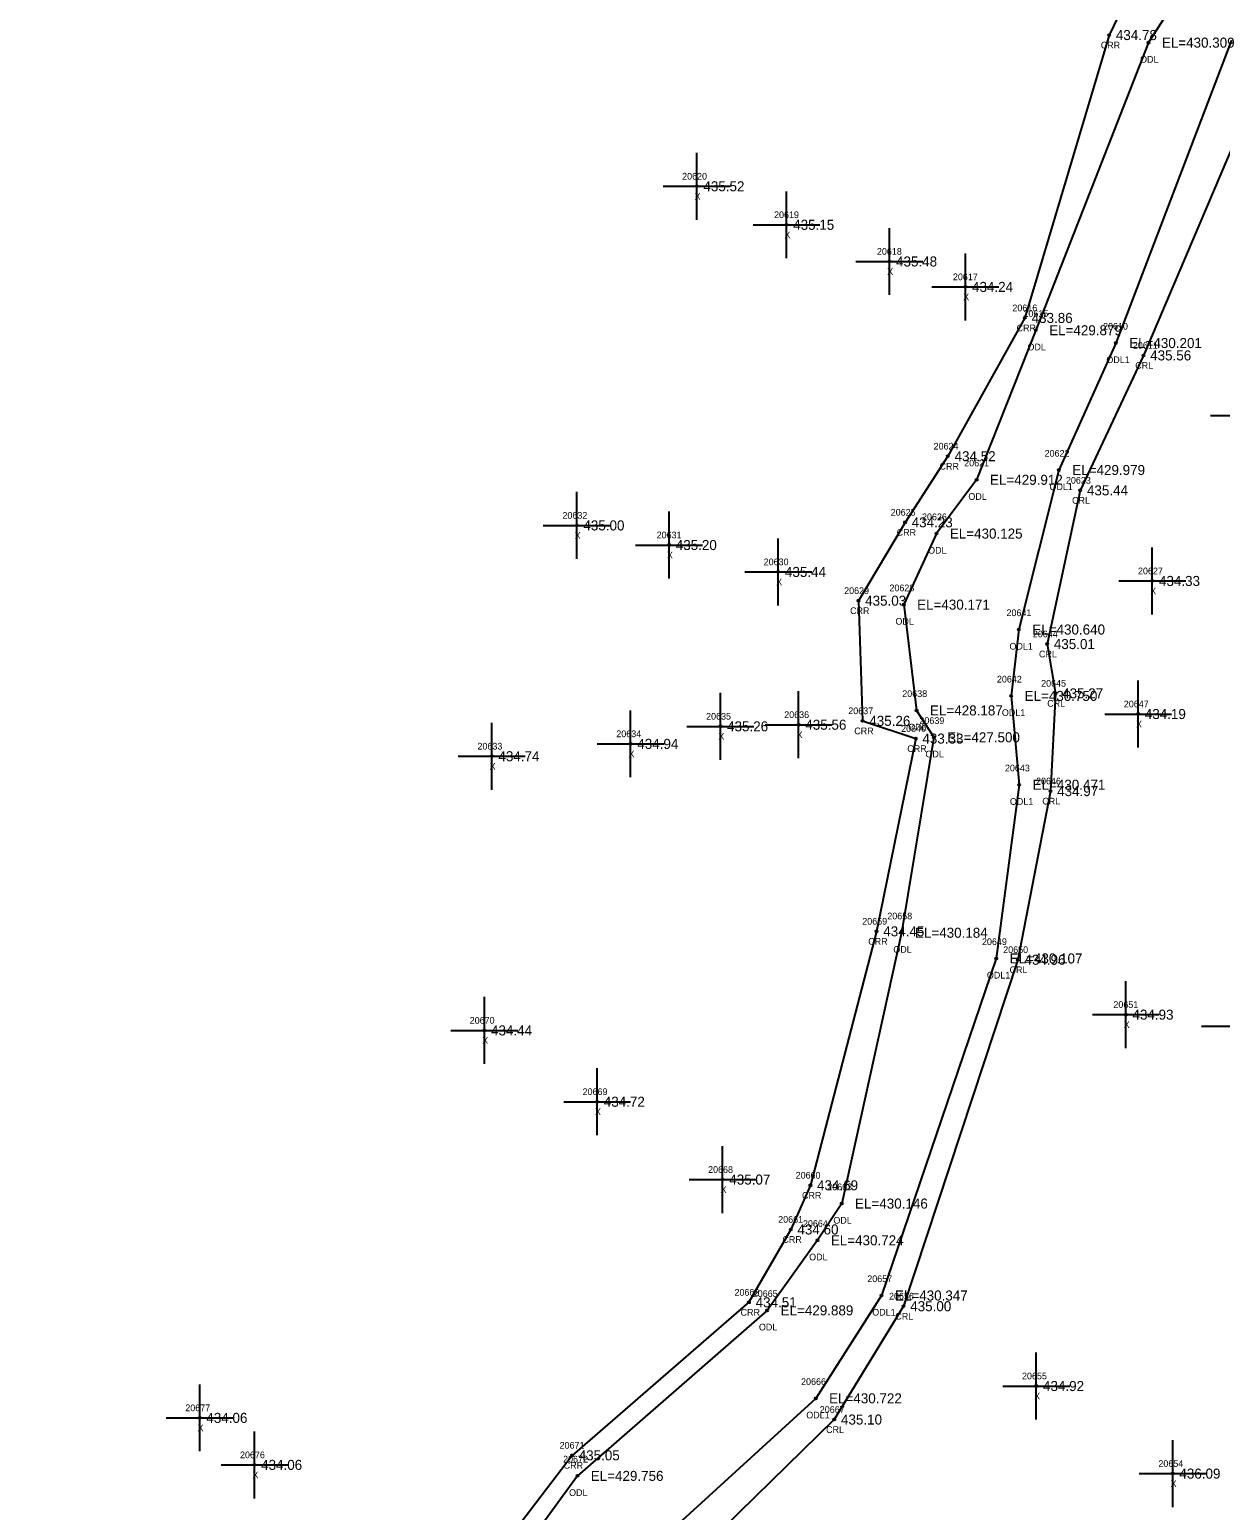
# Model space of a CAD drawing. Extents: x 1613836 to 1615109, y 777151 to 778248.
# Drawn here: x 1614274.4 to 1614452.4, y 777451 to 777672.3 of the extents above; entities that cross this region are included whole.
import ezdxf

# ---------------------------------------------------------------- set-up
doc = ezdxf.new("R2010")
doc.units = 0
for name, color, linetype in [('RD_EX_H2O', 7, 'Continuous'), ('RD_EX_H2O_txCode', 7, 'Continuous'), ('RD_EX_Misc', 7, 'Continuous'), ('RD_EX_Misc_txCode', 7, 'Continuous'), ('RD_EX_TX_H2O_ELEV', 7, 'Continuous'), ('RD_EX_TX_Misc_ELEV', 7, 'Continuous'), ('RD_SMD_Locator', 7, 'Continuous')]:
    doc.layers.add(name, color=color, linetype=linetype)

msp = doc.modelspace()

# ---------------------------------------------------------------- linework, layer by layer
at = {"layer": 'RD_EX_H2O'}
for points in [[(1614444.52, 777689.77), (1614435.76, 777671.49), (1614423.17, 777629.21), (1614411.65, 777608.54), (1614405.24, 777598.66), (1614398.28, 777586.95), (1614398.9, 777568.99), (1614406.84, 777566.34), (1614400.99, 777537.53), (1614391.09, 777499.57), (1614388.16, 777492.97), (1614381.91, 777482.08), (1614355.46, 777459.21), (1614337.74, 777435.91)], [(1614451.34, 777685.51), (1614441.64, 777670.36), (1614424.79, 777627.37), (1614415.95, 777605.02), (1614409.94, 777596.98), (1614405.05, 777586.36), (1614406.98, 777570.55), (1614409.54, 777566.53), (1614404.73, 777537.32), (1614395.77, 777496.84), (1614392.15, 777491.35), (1614384.64, 777480.88), (1614356.26, 777456.14), (1614340.53, 777434.54)], [(1614454.05, 777670.72), (1614436.75, 777625.46), (1614428.25, 777606.48), (1614422.27, 777582.64), (1614421.12, 777572.72), (1614422.32, 777559.44), (1614418.89, 777533.48), (1614401.74, 777483.1), (1614391.89, 777467.73), (1614349.64, 777429.15), (1614339.78, 777409.85), (1614335.95, 777396.86), (1614325.72, 777389.21), (1614290.49, 777368.16), (1614258.86, 777343.9), (1614240.94, 777335.51), (1614216.63, 777330.83), (1614183.69, 777312.56), (1614168.44, 777300.41), (1614159.13, 777291.4), (1614144.06, 777280.87), (1614131.88, 777280.26), (1614120.23, 777291.04), (1614099.45, 777295.34)], [(1614459.87, 777668.19), (1614440.89, 777623.61), (1614431.44, 777603.44), (1614426.49, 777580.47), (1614427.73, 777573.1), (1614426.99, 777558.49), (1614422.1, 777533.28), (1614405.02, 777481.5), (1614394.67, 777464.56), (1614354.26, 777425.05), (1614343.94, 777405.8), (1614336.19, 777392.32), (1614327.17, 777384), (1614294.72, 777361.79), (1614260.51, 777340.05), (1614241.21, 777332.56), (1614218.51, 777327.29), (1614184.87, 777310.82), (1614170.3, 777296.09), (1614164.11, 777287.12), (1614144.8, 777274.41), (1614131.24, 777274.67), (1614118.95, 777276.86), (1614096.34, 777283.46)]]:
    msp.add_lwpolyline(points, dxfattribs=at)
at = {"layer": 'RD_EX_Misc'}
for p, q in [((1614374.1, 777643.89), (1614374.1, 777653.89)), ((1614369.1, 777648.89), (1614379.1, 777648.89)), ((1614387.52, 777638.13), (1614387.52, 777648.13)), ((1614382.52, 777643.13), (1614392.52, 777643.13)), ((1614402.9, 777632.65), (1614402.9, 777642.65)), ((1614414.26, 777628.85), (1614414.26, 777638.85)), ((1614397.9, 777637.65), (1614407.9, 777637.65)), ((1614409.26, 777633.85), (1614419.26, 777633.85)), ((1614450.89, 777614.61), (1614460.89, 777614.61)), ((1614356.16, 777593.2), (1614356.16, 777603.2)), ((1614369.97, 777590.27), (1614369.97, 777600.27)), ((1614351.16, 777598.2), (1614361.16, 777598.2)), ((1614386.29, 777586.25), (1614386.29, 777596.25)), ((1614364.97, 777595.27), (1614374.97, 777595.27)), ((1614442.21, 777584.9), (1614442.21, 777594.9)), ((1614381.29, 777591.25), (1614391.29, 777591.25)), ((1614437.21, 777589.9), (1614447.21, 777589.9)), ((1614440.09, 777565.01), (1614440.09, 777575.01)), ((1614377.64, 777563.17), (1614377.64, 777573.17)), ((1614389.34, 777563.41), (1614389.34, 777573.41)), ((1614364.22, 777560.55), (1614364.22, 777570.55)), ((1614435.09, 777570.01), (1614445.09, 777570.01)), ((1614343.46, 777558.7), (1614343.46, 777568.7)), ((1614372.64, 777568.17), (1614382.64, 777568.17)), ((1614384.34, 777568.41), (1614394.34, 777568.41)), ((1614359.22, 777565.55), (1614369.22, 777565.55)), ((1614338.46, 777563.7), (1614348.46, 777563.7)), ((1614438.25, 777520.08), (1614438.25, 777530.08)), ((1614342.35, 777517.72), (1614342.35, 777527.72)), ((1614433.25, 777525.08), (1614443.25, 777525.08)), ((1614449.55, 777523.38), (1614459.55, 777523.38)), ((1614337.35, 777522.72), (1614347.35, 777522.72)), ((1614359.21, 777507.06), (1614359.21, 777517.06)), ((1614354.21, 777512.06), (1614364.21, 777512.06)), ((1614377.97, 777495.43), (1614377.97, 777505.43)), ((1614372.97, 777500.43), (1614382.97, 777500.43)), ((1614424.87, 777464.57), (1614424.87, 777474.57)), ((1614299.79, 777459.81), (1614299.79, 777469.81)), ((1614419.87, 777469.57), (1614429.87, 777469.57)), ((1614294.79, 777464.81), (1614304.79, 777464.81)), ((1614307.98, 777452.78), (1614307.98, 777462.78)), ((1614445.26, 777451.48), (1614445.26, 777461.48)), ((1614302.98, 777457.78), (1614312.98, 777457.78)), ((1614440.26, 777456.48), (1614450.26, 777456.48))]:
    msp.add_line(p, q, dxfattribs=at)
at = {"layer": 'RD_SMD_Locator'}
for centre in [(1614435.76, 777671.49), (1614441.64, 777670.36), (1614374.1, 777648.89), (1614387.52, 777643.13), (1614402.9, 777637.65), (1614414.26, 777633.85), (1614423.17, 777629.21), (1614424.79, 777627.37), (1614436.75, 777625.46), (1614440.89, 777623.61), (1614411.65, 777608.54), (1614415.95, 777605.02), (1614428.25, 777606.48), (1614431.44, 777603.44), (1614356.16, 777598.2), (1614405.24, 777598.66), (1614409.94, 777596.98), (1614369.97, 777595.27), (1614386.29, 777591.25), (1614442.21, 777589.9), (1614398.28, 777586.95), (1614405.05, 777586.36), (1614422.27, 777582.64), (1614426.49, 777580.47), (1614421.12, 777572.72), (1614427.73, 777573.1), (1614406.98, 777570.55), (1614440.09, 777570.01), (1614377.64, 777568.17), (1614389.34, 777568.41), (1614398.9, 777568.99), (1614364.22, 777565.55), (1614406.84, 777566.34), (1614409.54, 777566.53), (1614343.46, 777563.7), (1614422.32, 777559.44), (1614426.99, 777558.49), (1614400.99, 777537.53), (1614404.73, 777537.32), (1614418.89, 777533.48), (1614422.1, 777533.28), (1614438.25, 777525.08), (1614342.35, 777522.72), (1614359.21, 777512.06), (1614377.97, 777500.43), (1614391.09, 777499.57), (1614395.77, 777496.84), (1614388.16, 777492.97), (1614392.15, 777491.35), (1614401.74, 777483.1), (1614381.91, 777482.08), (1614384.64, 777480.88), (1614405.02, 777481.5), (1614424.87, 777469.57), (1614391.89, 777467.73), (1614299.79, 777464.81), (1614394.67, 777464.56), (1614355.46, 777459.21), (1614307.98, 777457.78), (1614445.26, 777456.48), (1614356.26, 777456.14)]:
    msp.add_circle(centre, 0.15, dxfattribs=at)

# ---------------------------------------------------------------- texts
at = {"layer": 'RD_EX_H2O_txCode'}
for s, p in [('CRR', (1614434.51, 777669.49)), ('ODL', (1614440.39, 777667.36)), ('20616', (1614421.29, 777630.21)), ('20615', (1614422.94, 777629.37)), ('CRR', (1614421.92, 777627.21)), ('20610', (1614434.85, 777627.46)), ('ODL', (1614423.55, 777624.37)), ('20611', (1614439.31, 777624.61)), ('ODL1', (1614435.34, 777622.46)), ('CRL', (1614439.66, 777621.61)), ('20624', (1614409.51, 777609.54)), ('20622', (1614426.11, 777608.48)), ('CRR', (1614410.4, 777606.54)), ('20621', (1614414.09, 777607.02)), ('20623', (1614429.3, 777604.44)), ('ODL', (1614414.71, 777602.02)), ('ODL1', (1614426.84, 777603.48)), ('20625', (1614403.1, 777599.66)), ('CRL', (1614430.21, 777601.44)), ('20626', (1614407.78, 777598.98)), ('CRR', (1614403.99, 777596.66)), ('ODL', (1614408.7, 777593.98)), ('20628', (1614402.91, 777588.36)), ('20629', (1614396.14, 777587.95)), ('CRR', (1614397.03, 777584.95)), ('20641', (1614420.41, 777584.64)), ('ODL', (1614403.81, 777583.36)), ('ODL1', (1614420.86, 777579.64)), ('20644', (1614424.35, 777581.47)), ('CRL', (1614425.27, 777578.47)), ('20642', (1614418.98, 777574.72)), ('20645', (1614425.59, 777574.1)), ('20638', (1614404.83, 777572.55)), ('CRL', (1614426.5, 777571.1)), ('20637', (1614396.76, 777569.99)), ('20639', (1614407.39, 777568.53)), ('ODL1', (1614419.72, 777569.72)), ('CRR', (1614397.65, 777566.99)), ('20640', (1614404.66, 777567.34)), ('ODL', (1614405.73, 777567.55)), ('CRR', (1614405.58, 777564.34)), ('ODL', (1614408.29, 777563.53)), ('20643', (1614420.18, 777561.44)), ('20646', (1614424.83, 777559.49)), ('ODL1', (1614420.92, 777556.44)), ('CRL', (1614425.76, 777556.49)), ('20659', (1614398.85, 777538.53)), ('20658', (1614402.59, 777539.32)), ('CRR', (1614399.74, 777535.53)), ('20649', (1614416.75, 777535.48)), ('ODL', (1614403.49, 777534.32)), ('20650', (1614419.92, 777534.28)), ('CRL', (1614420.87, 777531.28)), ('ODL1', (1614417.48, 777530.48)), ('20660', (1614388.89, 777500.57)), ('CRR', (1614389.84, 777497.57)), ('20663', (1614393.61, 777498.84)), ('20661', (1614386.28, 777493.97)), ('20664', (1614389.98, 777493.35)), ('ODL', (1614394.53, 777493.84)), ('CRR', (1614386.91, 777490.97)), ('ODL', (1614390.91, 777488.35)), ('20657', (1614399.6, 777485.1)), ('20662', (1614379.75, 777483.08)), ('20665', (1614382.48, 777482.88)), ('20656', (1614402.85, 777482.5)), ('CRR', (1614380.66, 777480.08)), ('ODL1', (1614400.34, 777480.1)), ('ODL', (1614383.4, 777477.88)), ('CRL', (1614403.79, 777479.5)), ('20666', (1614389.7, 777469.73)), ('ODL1', (1614390.48, 777464.73)), ('20667', (1614392.5, 777465.56)), ('CRL', (1614393.44, 777462.56)), ('20671', (1614353.6, 777460.21)), ('20672', (1614354.12, 777458.14)), ('CRR', (1614354.21, 777457.21)), ('ODL', (1614355.02, 777453.14))]:
    msp.add_text(s, height=1, dxfattribs=at).set_placement(p)
at = {"layer": 'RD_EX_Misc_txCode'}
for s, p in [('20620', (1614371.92, 777649.89)), ('X', (1614373.78, 777646.89)), ('20619', (1614385.66, 777644.13)), ('X', (1614387.21, 777641.13)), ('20618', (1614401.04, 777638.65)), ('X', (1614402.58, 777635.65)), ('20617', (1614412.4, 777634.85)), ('X', (1614413.94, 777631.85)), ('20632', (1614354.02, 777599.2)), ('X', (1614355.85, 777596.2)), ('20631', (1614368.11, 777596.27)), ('X', (1614369.65, 777593.27)), ('20630', (1614384.11, 777592.25)), ('20627', (1614440.07, 777590.9)), ('X', (1614385.98, 777589.25)), ('X', (1614441.9, 777587.9)), ('20647', (1614437.95, 777571.01)), ('20635', (1614375.5, 777569.17)), ('20636', (1614387.18, 777569.41)), ('20634', (1614362.08, 777566.55)), ('X', (1614377.33, 777566.17)), ('X', (1614389.03, 777566.41)), ('X', (1614439.78, 777568.01)), ('20633', (1614341.32, 777564.7)), ('X', (1614343.14, 777561.7)), ('X', (1614363.9, 777563.55)), ('20651', (1614436.39, 777526.08)), ('20670', (1614340.16, 777523.72)), ('X', (1614437.94, 777523.08)), ('X', (1614342.03, 777520.72)), ('20669', (1614357.04, 777513.06)), ('X', (1614358.89, 777510.06)), ('20668', (1614375.8, 777501.43)), ('X', (1614377.66, 777498.43)), ('20655', (1614422.73, 777470.57)), ('X', (1614424.55, 777467.57)), ('20677', (1614297.64, 777465.81)), ('X', (1614299.47, 777462.81)), ('20676', (1614305.82, 777458.78)), ('X', (1614307.67, 777455.78)), ('20654', (1614443.12, 777457.48)), ('X', (1614444.95, 777454.48))]:
    msp.add_text(s, height=1, dxfattribs=at).set_placement(p)
at = {"layer": 'RD_EX_TX_H2O_ELEV'}
for s, p in [('434.78', (1614436.76, 777670.74)), ('EL=430.309', (1614443.64, 777669.61)), ('433.86', (1614424.17, 777628.46)), ('EL=429.879', (1614426.79, 777626.62)), ('EL=430.201', (1614438.75, 777624.71)), ('435.56', (1614441.89, 777622.86)), ('434.52', (1614412.65, 777607.79)), ('EL=429.979', (1614430.25, 777605.73)), ('EL=429.912', (1614417.95, 777604.27)), ('435.44', (1614432.44, 777602.69)), ('434.23', (1614406.24, 777597.91)), ('EL=430.125', (1614411.94, 777596.23)), ('435.03', (1614399.28, 777586.2)), ('EL=430.171', (1614407.05, 777585.61)), ('EL=430.640', (1614424.27, 777581.89)), ('435.01', (1614427.49, 777579.72)), ('435.27', (1614428.73, 777572.35)), ('EL=430.750', (1614423.12, 777571.97)), ('435.26', (1614399.9, 777568.24)), ('EL=428.187', (1614408.98, 777569.8)), ('433.33', (1614407.84, 777565.59)), ('EL=427.500', (1614411.54, 777565.78)), ('EL=430.471', (1614424.32, 777558.69)), ('434.97', (1614427.99, 777557.74)), ('434.45', (1614401.99, 777536.78)), ('EL=430.184', (1614406.73, 777536.57)), ('EL=430.107', (1614420.89, 777532.73)), ('434.96', (1614423.1, 777532.53)), ('434.69', (1614392.09, 777498.82)), ('EL=430.146', (1614397.77, 777496.09)), ('434.60', (1614389.16, 777492.22)), ('EL=430.724', (1614394.15, 777490.6)), ('EL=430.347', (1614403.74, 777482.35)), ('434.51', (1614382.91, 777481.33)), ('EL=429.889', (1614386.64, 777480.13)), ('435.00', (1614406.02, 777480.75)), ('EL=430.722', (1614393.89, 777466.98)), ('435.10', (1614395.67, 777463.81)), ('435.05', (1614356.46, 777458.46)), ('EL=429.756', (1614358.26, 777455.39))]:
    msp.add_text(s, height=1.5, dxfattribs=at).set_placement(p)
at = {"layer": 'RD_EX_TX_Misc_ELEV'}
for s, p in [('435.52', (1614375.1, 777648.14)), ('435.15', (1614388.52, 777642.38)), ('435.48', (1614403.9, 777636.9)), ('434.24', (1614415.26, 777633.1)), ('435.00', (1614357.16, 777597.45)), ('435.20', (1614370.97, 777594.52)), ('435.44', (1614387.29, 777590.5)), ('434.33', (1614443.21, 777589.15)), ('434.19', (1614441.09, 777569.26)), ('435.26', (1614378.64, 777567.42)), ('435.56', (1614390.34, 777567.66)), ('434.94', (1614365.22, 777564.8)), ('434.74', (1614344.46, 777562.95)), ('434.93', (1614439.25, 777524.33)), ('434.44', (1614343.35, 777521.97)), ('434.72', (1614360.21, 777511.31)), ('435.07', (1614378.97, 777499.68)), ('434.92', (1614425.87, 777468.82)), ('434.06', (1614300.79, 777464.06)), ('434.06', (1614308.98, 777457.03)), ('436.09', (1614446.26, 777455.73))]:
    msp.add_text(s, height=1.5, dxfattribs=at).set_placement(p)

doc.saveas('drawing.dxf')
